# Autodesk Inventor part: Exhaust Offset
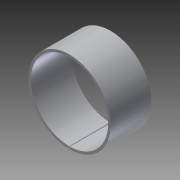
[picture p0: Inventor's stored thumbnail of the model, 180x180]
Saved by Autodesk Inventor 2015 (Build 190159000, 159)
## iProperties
Created: 2007-02
Part Number: Exhaust Offset
Material: Aluminum-6061
Document SubType Name: Sheet Metal
Designer: Autodesk, Inc.
Mass: 129.509 g
Surface Area: 335.49 cm^2
Volume: 47.7894 cm^3
Density: 2.71 g/cm^3
Sheet Metal Rule: Default
Appearance: Aluminum - Flat
Author: Autodesk, Inc.
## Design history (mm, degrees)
node "Contour Flange1"
  sketch "Sketch1"
    geometry: L1 (0.5, 49.29)-(-0.5, 49.29); L2 (-0.5, 49.29)-(-0.5, 65.844); L3 (-0.5, 65.844)-(0.5, 65.844); L4 (0.5, 65.844)-(0.5, 49.29); L5 (0, 110.149)-(0, 65.844); C1 r 25.4 at (0, 110.149); A1 r 50.8 centre (0, 110.149) between (0.5, 59.351) and (-0.5, 59.351)
    constraints: 10 end point, 2 centre point, 2 parallel, 2 point on circle, 2 point on line, 1 horizontal, 1 midpoint, 1 perpendicular, 1 vertical
    dimensions: "d0" = 101.6 diameter of A1; "d1" = 1 distance of L1.start L1.end
body "Solid1"
face "Plate1" dims "d2" = 3.048 (= BendReliefWidth), "d3" = 1.524 (= BendReliefDepth), "d4" = 6.096 (= MinimumRemnant), "d5" = 3.048 (= BendRadius), "d6" = 50.8, "d7" = 3.048 (= BendRadius), "d8" = 3.048, "d9" = 12.192 (= CornerReliefSize), "d10" = 3.048 (= Thickness), "d11" = 3.048 (= JacobiRadiusSize), "SeamGap" = 0.00508, "Thickness" = 3.048
bend "Bend1" dims "d2" = 3.048 (= BendReliefWidth), "d3" = 1.524 (= BendReliefDepth), "d4" = 6.096 (= MinimumRemnant), "d5" = 3.048 (= BendRadius), "d7" = 3.048 (= BendRadius), "d8" = 3.048, "SeamGap" = 0.00508, "Thickness" = 3.048
feature "Corner1" dims "d8" = 3.048, "d9" = 12.192 (= CornerReliefSize), "d10" = 3.048 (= Thickness), "d11" = 3.048 (= JacobiRadiusSize)
other parameters: "BendRadius" = 3.048 (= Thickness), "BendReliefWidth" = 3.048 (= Thickness), "BendReliefDepth" = 1.524 (= 0.5 x Thickness), "CornerReliefSize" = 12.192 (= 4 x Thickness), "MinimumRemnant" = 6.096 (= 2 x Thickness), "TransitionRadius" = 3.048 (= BendRadius), "JacobiRadiusSize" = 3.048 (= Thickness), "GapSize" = 3.048 (= Thickness)
